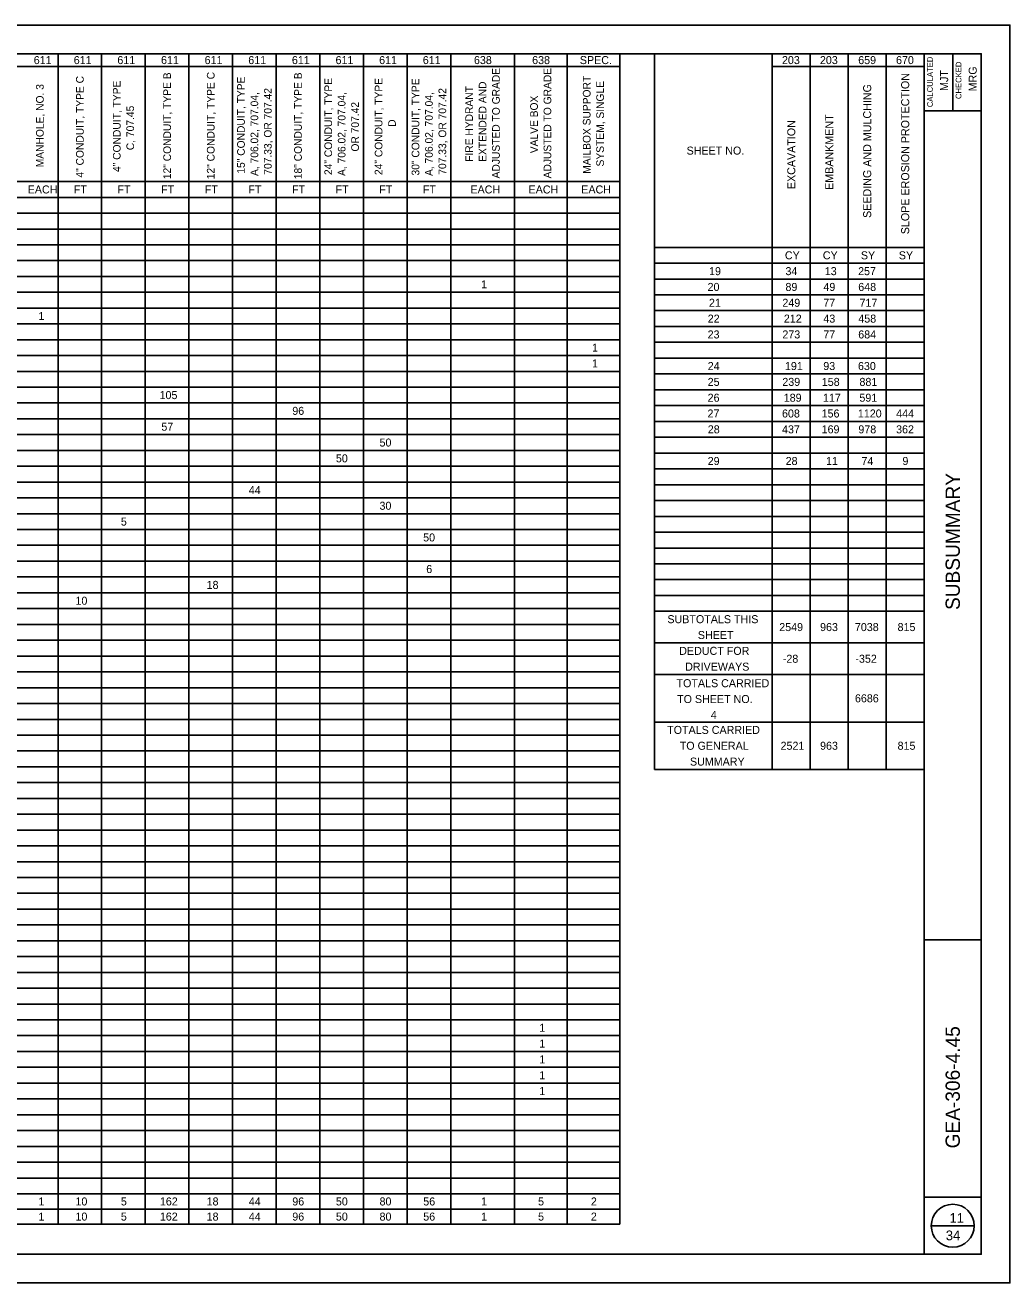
# Model space of a CAD drawing. Extents: x -16 to 102, y -13 to 9.
# Drawn here: x 0.4 to 17.63, y -12.91 to 9.09 of the extents above; entities that cross this region are included whole.
import ezdxf

# ---------------------------------------------------------------- set-up
doc = ezdxf.new("R2010")
doc.units = 0
for name, color, linetype in [('PV_P_EOP', 7, 'Continuous'), ('SH_Border', 7, 'Continuous'), ('SH_Cut_Line', 7, 'Continuous'), ('SH_Data', 7, 'Continuous'), ('SH_Text', 7, 'Continuous'), ('TX_P_1', 7, 'Continuous')]:
    doc.layers.add(name, color=color, linetype=linetype)

msp = doc.modelspace()

# ---------------------------------------------------------------- linework, layer by layer
at = {"layer": 'SH_Border'}
for p, q in [((16.129, -12.407), (16.129, 8.593)), ((16.629, 8.593), (16.629, 7.593)), ((16.129, 7.593), (17.129, 7.593)), ((16.129, -6.907), (17.129, -6.907)), ((16.129, -11.407), (17.129, -11.407))]:
    msp.add_line(p, q, dxfattribs=at)
msp.add_lwpolyline([(-14.371, 8.593), (17.129, 8.593), (17.129, -12.407), (-14.371, -12.407)], close=True, dxfattribs=at)
at = {"layer": 'SH_Cut_Line'}
msp.add_lwpolyline([(-16.371, -12.907), (17.629, -12.907), (17.629, 9.093), (-16.371, 9.093)], close=True, dxfattribs=at)
at = {"layer": 'SH_Data'}
msp.add_line((16.254, -11.907), (17.004, -11.907), dxfattribs=at)
msp.add_circle((16.629, -11.907), 0.375, dxfattribs=at)
at = {"layer": 'SH_Text'}
for p, q in [((-10.002, 8.593), (1.736, 8.593)), ((0.973, 8.593), (0.973, -11.881)), ((1.736, 8.593), (3.263, 8.593)), ((1.736, 8.593), (1.736, -11.881)), ((2.5, 8.593), (2.5, -11.881)), ((3.263, 8.593), (6.317, 8.593)), ((3.263, 8.593), (3.263, -11.881)), ((4.027, 8.593), (4.027, -11.881)), ((4.79, 8.593), (4.79, -11.881)), ((5.554, 8.593), (5.554, -11.881)), ((6.317, 8.593), (10.803, 8.593)), ((6.317, 8.593), (6.317, -11.881)), ((7.081, 8.593), (7.081, -11.881)), ((7.844, 8.593), (7.844, -11.881)), ((8.958, 8.593), (8.958, -11.881)), ((9.88, 8.593), (9.88, -11.881)), ((10.803, 8.593), (10.803, -11.881)), ((11.413, 8.593), (16.129, 8.593)), ((11.413, 8.593), (11.413, 5.206)), ((13.472, 8.593), (13.472, 5.206)), ((14.136, 8.593), (14.136, 5.206)), ((14.8, 8.593), (14.8, 5.206)), ((15.465, 8.593), (15.465, 5.206)), ((16.129, 8.593), (16.129, 5.206)), ((-7.871, 8.372), (1.736, 8.372)), ((1.736, 8.372), (3.263, 8.372)), ((3.263, 8.372), (6.317, 8.372)), ((6.317, 8.372), (10.803, 8.372)), ((13.472, 8.372), (16.129, 8.372)), ((-7.871, 6.357), (1.736, 6.357)), ((1.736, 6.357), (3.263, 6.357)), ((3.263, 6.357), (6.317, 6.357)), ((6.317, 6.357), (10.803, 6.357)), ((-10.002, 6.081), (1.736, 6.081)), ((1.736, 6.081), (3.263, 6.081)), ((3.263, 6.081), (6.317, 6.081)), ((6.317, 6.081), (10.803, 6.081)), ((-10.002, 5.804), (1.736, 5.804)), ((1.736, 5.804), (3.263, 5.804)), ((3.263, 5.804), (6.317, 5.804)), ((6.317, 5.804), (10.803, 5.804)), ((-10.002, 5.527), (1.736, 5.527)), ((1.736, 5.527), (3.263, 5.527)), ((3.263, 5.527), (6.317, 5.527)), ((6.317, 5.527), (10.803, 5.527)), ((-10.002, 5.251), (1.736, 5.251)), ((1.736, 5.251), (3.263, 5.251)), ((3.263, 5.251), (6.317, 5.251)), ((6.317, 5.251), (10.803, 5.251)), ((11.413, 5.206), (16.129, 5.206)), ((11.413, 5.206), (11.413, 4.375)), ((13.472, 5.206), (13.472, 4.375)), ((14.136, 5.206), (14.136, 4.375)), ((14.8, 5.206), (14.8, 4.375)), ((15.465, 5.206), (15.465, 4.375)), ((16.129, 5.206), (16.129, 4.375)), ((-10.002, 4.974), (1.736, 4.974)), ((1.736, 4.974), (3.263, 4.974)), ((3.263, 4.974), (6.317, 4.974)), ((6.317, 4.974), (10.803, 4.974)), ((11.413, 4.929), (16.129, 4.929)), ((-10.002, 4.697), (1.736, 4.697)), ((1.736, 4.697), (3.263, 4.697)), ((3.263, 4.697), (6.317, 4.697)), ((6.317, 4.697), (10.803, 4.697)), ((11.413, 4.652), (16.129, 4.652)), ((-10.002, 4.421), (1.736, 4.421)), ((1.736, 4.421), (3.263, 4.421)), ((3.263, 4.421), (6.317, 4.421)), ((6.317, 4.421), (10.803, 4.421)), ((11.413, 4.375), (16.129, 4.375)), ((11.413, 4.375), (11.413, -0.883)), ((13.472, 4.375), (13.472, -0.883)), ((14.136, 4.375), (14.136, -0.883)), ((14.8, 4.375), (14.8, -0.883)), ((15.465, 4.375), (15.465, -0.883)), ((16.129, 4.375), (16.129, -0.883)), ((-10.002, 4.144), (1.736, 4.144)), ((1.736, 4.144), (3.263, 4.144)), ((3.263, 4.144), (6.317, 4.144)), ((6.317, 4.144), (10.803, 4.144)), ((11.413, 4.099), (16.129, 4.099)), ((-10.002, 3.867), (1.736, 3.867)), ((1.736, 3.867), (3.263, 3.867)), ((3.263, 3.867), (6.317, 3.867)), ((6.317, 3.867), (10.803, 3.867)), ((11.413, 3.822), (16.129, 3.822)), ((-10.002, 3.591), (1.736, 3.591)), ((1.736, 3.591), (3.263, 3.591)), ((3.263, 3.591), (6.317, 3.591)), ((6.317, 3.591), (10.803, 3.591)), ((11.413, 3.545), (16.129, 3.545)), ((-10.002, 3.314), (1.736, 3.314)), ((1.736, 3.314), (3.263, 3.314)), ((3.263, 3.314), (6.317, 3.314)), ((6.317, 3.314), (10.803, 3.314)), ((11.413, 3.268), (16.129, 3.268)), ((-10.002, 3.037), (1.736, 3.037)), ((1.736, 3.037), (3.263, 3.037)), ((3.263, 3.037), (6.317, 3.037)), ((6.317, 3.037), (10.803, 3.037)), ((11.413, 2.992), (16.129, 2.992)), ((-10.002, 2.761), (1.736, 2.761)), ((1.736, 2.761), (3.263, 2.761)), ((3.263, 2.761), (6.317, 2.761)), ((6.317, 2.761), (10.803, 2.761)), ((11.413, 2.715), (16.129, 2.715)), ((-10.002, 2.484), (1.736, 2.484)), ((1.736, 2.484), (3.263, 2.484)), ((3.263, 2.484), (6.317, 2.484)), ((6.317, 2.484), (10.803, 2.484)), ((11.413, 2.438), (16.129, 2.438)), ((-10.002, 2.207), (1.736, 2.207)), ((1.736, 2.207), (3.263, 2.207)), ((3.263, 2.207), (6.317, 2.207)), ((6.317, 2.207), (10.803, 2.207)), ((11.413, 2.161), (16.129, 2.161)), ((-10.002, 1.931), (1.736, 1.931)), ((1.736, 1.931), (3.263, 1.931)), ((3.263, 1.931), (6.317, 1.931)), ((6.317, 1.931), (10.803, 1.931)), ((11.413, 1.885), (16.129, 1.885)), ((-10.002, 1.654), (1.736, 1.654)), ((1.736, 1.654), (3.263, 1.654)), ((3.263, 1.654), (6.317, 1.654)), ((6.317, 1.654), (10.803, 1.654)), ((11.413, 1.608), (16.129, 1.608)), ((-10.002, 1.377), (1.736, 1.377)), ((1.736, 1.377), (3.263, 1.377)), ((3.263, 1.377), (6.317, 1.377)), ((6.317, 1.377), (10.803, 1.377)), ((11.413, 1.331), (16.129, 1.331)), ((-10.002, 1.101), (1.736, 1.101)), ((1.736, 1.101), (3.263, 1.101)), ((3.263, 1.101), (6.317, 1.101)), ((6.317, 1.101), (10.803, 1.101)), ((11.413, 1.054), (16.129, 1.054)), ((-10.002, 0.824), (1.736, 0.824)), ((1.736, 0.824), (3.263, 0.824)), ((3.263, 0.824), (6.317, 0.824)), ((6.317, 0.824), (10.803, 0.824)), ((11.413, 0.778), (16.129, 0.778)), ((-10.002, 0.547), (1.736, 0.547)), ((1.736, 0.547), (3.263, 0.547)), ((3.263, 0.547), (6.317, 0.547)), ((6.317, 0.547), (10.803, 0.547)), ((11.413, 0.501), (16.129, 0.501)), ((-10.002, 0.271), (1.736, 0.271)), ((1.736, 0.271), (3.263, 0.271)), ((3.263, 0.271), (6.317, 0.271)), ((6.317, 0.271), (10.803, 0.271)), ((11.413, 0.224), (16.129, 0.224)), ((-10.002, -0.006), (1.736, -0.006)), ((1.736, -0.006), (3.263, -0.006)), ((3.263, -0.006), (6.317, -0.006)), ((6.317, -0.006), (10.803, -0.006)), ((11.413, -0.053), (16.129, -0.053)), ((-10.002, -0.283), (1.736, -0.283)), ((1.736, -0.283), (3.263, -0.283)), ((3.263, -0.283), (6.317, -0.283)), ((6.317, -0.283), (10.803, -0.283)), ((11.413, -0.329), (16.129, -0.329)), ((-10.002, -0.56), (1.736, -0.56)), ((1.736, -0.56), (3.263, -0.56)), ((3.263, -0.56), (6.317, -0.56)), ((6.317, -0.56), (10.803, -0.56)), ((11.413, -0.606), (16.129, -0.606)), ((-10.002, -0.836), (1.736, -0.836)), ((1.736, -0.836), (3.263, -0.836)), ((3.263, -0.836), (6.317, -0.836)), ((6.317, -0.836), (10.803, -0.836)), ((11.413, -0.883), (16.129, -0.883)), ((11.413, -0.883), (11.413, -3.927)), ((13.472, -0.883), (13.472, -3.927)), ((14.136, -0.883), (14.136, -3.927)), ((14.8, -0.883), (14.8, -3.927)), ((15.465, -0.883), (15.465, -3.927)), ((16.129, -0.883), (16.129, -3.927)), ((-10.002, -1.113), (1.736, -1.113)), ((1.736, -1.113), (3.263, -1.113)), ((3.263, -1.113), (6.317, -1.113)), ((6.317, -1.113), (10.803, -1.113)), ((11.413, -1.16), (16.129, -1.16)), ((-10.002, -1.39), (1.736, -1.39)), ((1.736, -1.39), (3.263, -1.39)), ((3.263, -1.39), (6.317, -1.39)), ((6.317, -1.39), (10.803, -1.39)), ((-10.002, -1.666), (1.736, -1.666)), ((1.736, -1.666), (3.263, -1.666)), ((3.263, -1.666), (6.317, -1.666)), ((6.317, -1.666), (10.803, -1.666)), ((11.413, -1.713), (16.129, -1.713)), ((-10.002, -1.943), (1.736, -1.943)), ((1.736, -1.943), (3.263, -1.943)), ((3.263, -1.943), (6.317, -1.943)), ((6.317, -1.943), (10.803, -1.943)), ((-10.002, -2.22), (1.736, -2.22)), ((1.736, -2.22), (3.263, -2.22)), ((3.263, -2.22), (6.317, -2.22)), ((6.317, -2.22), (10.803, -2.22)), ((11.413, -2.267), (16.129, -2.267)), ((-10.002, -2.496), (1.736, -2.496)), ((1.736, -2.496), (3.263, -2.496)), ((3.263, -2.496), (6.317, -2.496)), ((6.317, -2.496), (10.803, -2.496)), ((-10.002, -2.773), (1.736, -2.773)), ((1.736, -2.773), (3.263, -2.773)), ((3.263, -2.773), (6.317, -2.773)), ((6.317, -2.773), (10.803, -2.773)), ((-10.002, -3.05), (1.736, -3.05)), ((1.736, -3.05), (3.263, -3.05)), ((3.263, -3.05), (6.317, -3.05)), ((6.317, -3.05), (10.803, -3.05)), ((11.413, -3.097), (16.129, -3.097)), ((-10.002, -3.326), (1.736, -3.326)), ((1.736, -3.326), (3.263, -3.326)), ((3.263, -3.326), (6.317, -3.326)), ((6.317, -3.326), (10.803, -3.326)), ((-10.002, -3.603), (1.736, -3.603)), ((1.736, -3.603), (3.263, -3.603)), ((3.263, -3.603), (6.317, -3.603)), ((6.317, -3.603), (10.803, -3.603)), ((-10.002, -3.88), (1.736, -3.88)), ((1.736, -3.88), (3.263, -3.88)), ((3.263, -3.88), (6.317, -3.88)), ((6.317, -3.88), (10.803, -3.88)), ((11.413, -3.927), (16.129, -3.927)), ((-10.002, -4.156), (1.736, -4.156)), ((1.736, -4.156), (3.263, -4.156)), ((3.263, -4.156), (6.317, -4.156)), ((6.317, -4.156), (10.803, -4.156)), ((-10.002, -4.433), (1.736, -4.433)), ((1.736, -4.433), (3.263, -4.433)), ((3.263, -4.433), (6.317, -4.433)), ((6.317, -4.433), (10.803, -4.433)), ((-10.002, -4.71), (1.736, -4.71)), ((1.736, -4.71), (3.263, -4.71)), ((3.263, -4.71), (6.317, -4.71)), ((6.317, -4.71), (10.803, -4.71)), ((-10.002, -4.986), (1.736, -4.986)), ((1.736, -4.986), (3.263, -4.986)), ((3.263, -4.986), (6.317, -4.986)), ((6.317, -4.986), (10.803, -4.986)), ((-10.002, -5.263), (1.736, -5.263)), ((1.736, -5.263), (3.263, -5.263)), ((3.263, -5.263), (6.317, -5.263)), ((6.317, -5.263), (10.803, -5.263)), ((-10.002, -5.54), (1.736, -5.54)), ((1.736, -5.54), (3.263, -5.54)), ((3.263, -5.54), (6.317, -5.54)), ((6.317, -5.54), (10.803, -5.54)), ((-10.002, -5.816), (1.736, -5.816)), ((1.736, -5.816), (3.263, -5.816)), ((3.263, -5.816), (6.317, -5.816)), ((6.317, -5.816), (10.803, -5.816)), ((-10.002, -6.093), (1.736, -6.093)), ((1.736, -6.093), (3.263, -6.093)), ((3.263, -6.093), (6.317, -6.093)), ((6.317, -6.093), (10.803, -6.093)), ((-10.002, -6.37), (1.736, -6.37)), ((1.736, -6.37), (3.263, -6.37)), ((3.263, -6.37), (6.317, -6.37)), ((6.317, -6.37), (10.803, -6.37)), ((-10.002, -6.646), (1.736, -6.646)), ((1.736, -6.646), (3.263, -6.646)), ((3.263, -6.646), (6.317, -6.646)), ((6.317, -6.646), (10.803, -6.646)), ((-10.002, -6.923), (1.736, -6.923)), ((1.736, -6.923), (3.263, -6.923)), ((3.263, -6.923), (6.317, -6.923)), ((6.317, -6.923), (10.803, -6.923)), ((-10.002, -7.2), (1.736, -7.2)), ((1.736, -7.2), (3.263, -7.2)), ((3.263, -7.2), (6.317, -7.2)), ((6.317, -7.2), (10.803, -7.2)), ((-10.002, -7.477), (1.736, -7.477)), ((1.736, -7.477), (3.263, -7.477)), ((3.263, -7.477), (6.317, -7.477)), ((6.317, -7.477), (10.803, -7.477)), ((-10.002, -7.753), (1.736, -7.753)), ((1.736, -7.753), (3.263, -7.753)), ((3.263, -7.753), (6.317, -7.753)), ((6.317, -7.753), (10.803, -7.753)), ((-10.002, -8.03), (1.736, -8.03)), ((1.736, -8.03), (3.263, -8.03)), ((3.263, -8.03), (6.317, -8.03)), ((6.317, -8.03), (10.803, -8.03)), ((-10.002, -8.307), (1.736, -8.307)), ((1.736, -8.307), (3.263, -8.307)), ((3.263, -8.307), (6.317, -8.307)), ((6.317, -8.307), (10.803, -8.307)), ((-10.002, -8.583), (1.736, -8.583)), ((1.736, -8.583), (3.263, -8.583)), ((3.263, -8.583), (6.317, -8.583)), ((6.317, -8.583), (10.803, -8.583)), ((-10.002, -8.86), (1.736, -8.86)), ((1.736, -8.86), (3.263, -8.86)), ((3.263, -8.86), (6.317, -8.86)), ((6.317, -8.86), (10.803, -8.86)), ((-10.002, -9.137), (1.736, -9.137)), ((1.736, -9.137), (3.263, -9.137)), ((3.263, -9.137), (6.317, -9.137)), ((6.317, -9.137), (10.803, -9.137)), ((-10.002, -9.413), (1.736, -9.413)), ((1.736, -9.413), (3.263, -9.413)), ((3.263, -9.413), (6.317, -9.413)), ((6.317, -9.413), (10.803, -9.413)), ((-10.002, -9.69), (1.736, -9.69)), ((1.736, -9.69), (3.263, -9.69)), ((3.263, -9.69), (6.317, -9.69)), ((6.317, -9.69), (10.803, -9.69)), ((-10.002, -9.967), (1.736, -9.967)), ((1.736, -9.967), (3.263, -9.967)), ((3.263, -9.967), (6.317, -9.967)), ((6.317, -9.967), (10.803, -9.967)), ((-10.002, -10.243), (1.736, -10.243)), ((1.736, -10.243), (3.263, -10.243)), ((3.263, -10.243), (6.317, -10.243)), ((6.317, -10.243), (10.803, -10.243)), ((-10.002, -10.52), (1.736, -10.52)), ((1.736, -10.52), (3.263, -10.52)), ((3.263, -10.52), (6.317, -10.52)), ((6.317, -10.52), (10.803, -10.52)), ((-10.002, -10.797), (1.736, -10.797)), ((1.736, -10.797), (3.263, -10.797)), ((3.263, -10.797), (6.317, -10.797)), ((6.317, -10.797), (10.803, -10.797)), ((-10.002, -11.073), (1.736, -11.073)), ((1.736, -11.073), (3.263, -11.073)), ((3.263, -11.073), (6.317, -11.073)), ((6.317, -11.073), (10.803, -11.073)), ((-10.002, -11.35), (1.736, -11.35)), ((1.736, -11.35), (3.263, -11.35)), ((3.263, -11.35), (6.317, -11.35)), ((6.317, -11.35), (10.803, -11.35)), ((-10.002, -11.616), (1.736, -11.616)), ((1.736, -11.616), (3.263, -11.616)), ((3.263, -11.616), (6.317, -11.616)), ((6.317, -11.616), (10.803, -11.616)), ((-10.002, -11.881), (1.736, -11.881)), ((1.736, -11.881), (3.263, -11.881)), ((3.263, -11.881), (6.317, -11.881)), ((6.317, -11.881), (10.803, -11.881))]:
    msp.add_line(p, q, dxfattribs=at)

# ---------------------------------------------------------------- texts
at = {"layer": 'PV_P_EOP'}
for s, height, p in [('SHEET NO.', 0.14, (11.972, 6.829)), ('SUBTOTALS THIS ', 0.14004, (11.636, -1.368)), ('SHEET', 0.14, (12.169, -1.645)), ('DEDUCT FOR ', 0.14004, (11.843, -1.922)), ('DRIVEWAYS', 0.14, (11.947, -2.198)), ('TOTALS CARRIED ', 0.14004, (11.796, -2.488)), (' TO SHEET NO.', 0.14004, (11.754, -2.765)), ('4', 0.14, (12.396, -3.042)), ('TOTALS CARRIED ', 0.14004, (11.632, -3.305)), (' TO GENERAL ', 0.14004, (11.8, -3.582)), ('SUMMARY', 0.14, (12.031, -3.859))]:
    msp.add_text(s, height=height, dxfattribs=at).set_placement(p)
at = {"layer": 'SH_Data'}
for s, height, p in [('CALCULATED', 0.1, (16.281, 7.658)), ('CHECKED', 0.1, (16.781, 7.801)), ('MJT', 0.14, (16.549, 7.942)), ('MRG', 0.14, (17.049, 7.935)), ('SUBSUMMARY', 0.25, (16.754, -1.137)), ('GEA-306-4.45', 0.25, (16.754, -10.555))]:
    msp.add_text(s, height=height, rotation=90, dxfattribs=at).set_placement(p)
at = {"layer": 'SH_Text'}
for s, p in [('11', (16.573, -11.857)), ('34', (16.508, -12.162))]:
    msp.add_text(s, height=0.17, dxfattribs=at).set_placement(p)
at = {"layer": 'TX_P_1'}
for s, p in [('611', (0.548, 8.412)), ('611', (1.248, 8.412)), ('611', (2.011, 8.412)), ('611', (2.775, 8.412)), ('611', (3.538, 8.412)), ('611', (4.302, 8.412)), ('611', (5.065, 8.412)), ('611', (5.829, 8.412)), ('611', (6.592, 8.412)), ('611', (7.356, 8.412)), ('638', (8.251, 8.412)), ('638', (9.269, 8.412)), ('SPEC.', (10.104, 8.412)), ('203', (13.641, 8.412)), ('203', (14.305, 8.412)), ('659', (14.975, 8.412)), ('670', (15.637, 8.412)), ('EACH', (0.442, 6.149)), ('FT', (1.249, 6.149)), ('FT', (2.013, 6.149)), ('FT', (2.776, 6.149)), ('FT', (3.54, 6.149)), ('FT', (4.303, 6.149)), ('FT', (5.067, 6.149)), ('FT', (5.83, 6.149)), ('FT', (6.594, 6.149)), ('FT', (7.357, 6.149)), ('EACH', (8.189, 6.149)), ('EACH', (9.207, 6.149)), ('EACH', (10.129, 6.149)), ('CY', (13.692, 4.997)), ('CY', (14.356, 4.997)), ('SY', (15.022, 4.997)), ('SY', (15.686, 4.997)), ('19', (12.365, 4.72)), ('34', (13.702, 4.72)), ('13', (14.39, 4.72)), ('257', (14.973, 4.72)), ('1', (8.376, 4.489)), ('20', (12.339, 4.444)), ('89', (13.702, 4.444)), ('49', (14.366, 4.444)), ('648', (14.976, 4.444)), ('21', (12.363, 4.167)), ('249', (13.648, 4.167)), ('77', (14.364, 4.167)), ('717', (14.998, 4.167)), ('1', (0.63, 3.936)), ('22', (12.342, 3.89)), ('212', (13.674, 3.89)), ('43', (14.365, 3.89)), ('458', (14.977, 3.89)), ('23', (12.34, 3.613)), ('273', (13.648, 3.613)), ('77', (14.364, 3.613)), ('684', (14.976, 3.613)), ('1', (10.317, 3.382)), ('1', (10.317, 3.106)), ('24', (12.342, 3.06)), ('191', (13.693, 3.06)), ('93', (14.364, 3.06)), ('630', (14.971, 3.06)), ('25', (12.341, 2.783)), ('239', (13.647, 2.783)), ('158', (14.338, 2.783)), ('881', (14.997, 2.783)), ('105', (2.749, 2.552)), ('26', (12.34, 2.506)), ('189', (13.672, 2.506)), ('117', (14.358, 2.506)), ('591', (14.996, 2.506)), ('96', (5.072, 2.276)), ('27', (12.338, 2.23)), ('608', (13.642, 2.23)), ('156', (14.335, 2.23)), ('1120', (14.969, 2.23)), ('444', (15.64, 2.23)), ('57', (2.781, 1.999)), ('28', (12.343, 1.953)), ('437', (13.642, 1.953)), ('169', (14.335, 1.953)), ('978', (14.978, 1.953)), ('362', (15.638, 1.953)), ('50', (6.599, 1.722)), ('50', (5.835, 1.446)), ('29', (12.341, 1.399)), ('28', (13.705, 1.399)), ('9', (15.749, 1.399)), ('11', (14.412, 1.399)), ('74', (15.032, 1.399)), ('44', (4.311, 0.892)), ('30', (6.598, 0.616)), ('5', (2.072, 0.339)), ('50', (7.362, 0.062)), ('6', (7.416, -0.491)), ('18', (3.573, -0.768)), ('10', (1.278, -1.045)), ('2549', (13.593, -1.506)), ('963', (14.308, -1.506)), ('7038', (14.917, -1.506)), ('815', (15.664, -1.506)), ('-28', (13.656, -2.06)), ('-352', (14.926, -2.06)), ('6686', (14.918, -2.752)), ('2521', (13.616, -3.582)), ('963', (14.308, -3.582)), ('815', (15.664, -3.582)), ('1', (9.394, -8.515)), ('1', (9.394, -8.792)), ('1', (9.394, -9.068)), ('1', (9.394, -9.345)), ('1', (9.394, -9.622)), ('1', (0.63, -11.553)), ('10', (1.278, -11.553)), ('5', (2.072, -11.553)), ('162', (2.755, -11.553)), ('18', (3.573, -11.553)), ('44', (4.311, -11.553)), ('96', (5.072, -11.553)), ('50', (5.835, -11.553)), ('80', (6.599, -11.553)), ('56', (7.364, -11.553)), ('1', (8.376, -11.553)), ('5', (9.373, -11.553)), ('2', (10.297, -11.553)), ('1', (0.63, -11.818)), ('10', (1.278, -11.818)), ('5', (2.072, -11.818)), ('162', (2.755, -11.818)), ('18', (3.573, -11.818)), ('44', (4.311, -11.818)), ('96', (5.072, -11.818)), ('50', (5.835, -11.818)), ('80', (6.599, -11.818)), ('56', (7.364, -11.818)), ('1', (8.376, -11.818)), ('5', (9.373, -11.818)), ('2', (10.297, -11.818))]:
    msp.add_text(s, height=0.14, dxfattribs=at).set_placement(p)
for s, height, p in [('4" CONDUIT, TYPE C', 0.13414, (1.422, 6.426)), ('12" CONDUIT, TYPE B', 0.13414, (2.949, 6.399)), ('12" CONDUIT, TYPE C', 0.13414, (3.712, 6.397)), ('15" CONDUIT, TYPE', 0.13414, (4.241, 6.495)), ('18" CONDUIT, TYPE B', 0.13414, (5.239, 6.398)), ('24" CONDUIT, TYPE', 0.13414, (5.768, 6.471)), ('24" CONDUIT, TYPE', 0.13414, (6.649, 6.471)), ('30" CONDUIT, TYPE', 0.13414, (7.295, 6.463)), ('ADJUSTED TO GRADE', 0.13414, (8.703, 6.412)), ('ADJUSTED TO GRADE', 0.13414, (9.604, 6.412)), ('MAILBOX SUPPORT', 0.13414, (10.291, 6.493)), ('SLOPE EROSION PROTECTION', 0.14004, (15.867, 5.436)), ('MANHOLE, NO. 3', 0.13414, (0.722, 6.607)), ('4" CONDUIT, TYPE', 0.13414, (2.068, 6.524)), ('707.33, OR 707.42', 0.13414, (4.711, 6.477)), ('707.33, OR 707.42', 0.13414, (7.765, 6.477)), ('FIRE HYDRANT', 0.13414, (8.234, 6.702)), ('EXTENDED AND', 0.13414, (8.468, 6.702)), ('SYSTEM, SINGLE', 0.13414, (10.526, 6.621)), ('SEEDING AND MULCHING', 0.14004, (15.202, 5.721)), ('A, 706.02, 707.04,', 0.13414, (4.476, 6.455)), ('A, 706.02, 707.04,', 0.13414, (6.003, 6.455)), ('OR 707.42', 0.1341, (6.238, 6.882)), ('A, 706.02, 707.04,', 0.13414, (7.53, 6.455)), ('VALVE BOX', 0.1341, (9.369, 6.853)), ('C, 707.45', 0.1341, (2.303, 6.906)), ('EMBANKMENT', 0.14, (14.538, 6.212)), ('D', 0.134, (6.884, 7.315)), ('EXCAVATION', 0.14, (13.874, 6.225))]:
    msp.add_text(s, height=height, rotation=90, dxfattribs=at).set_placement(p)

doc.saveas('drawing.dxf')
